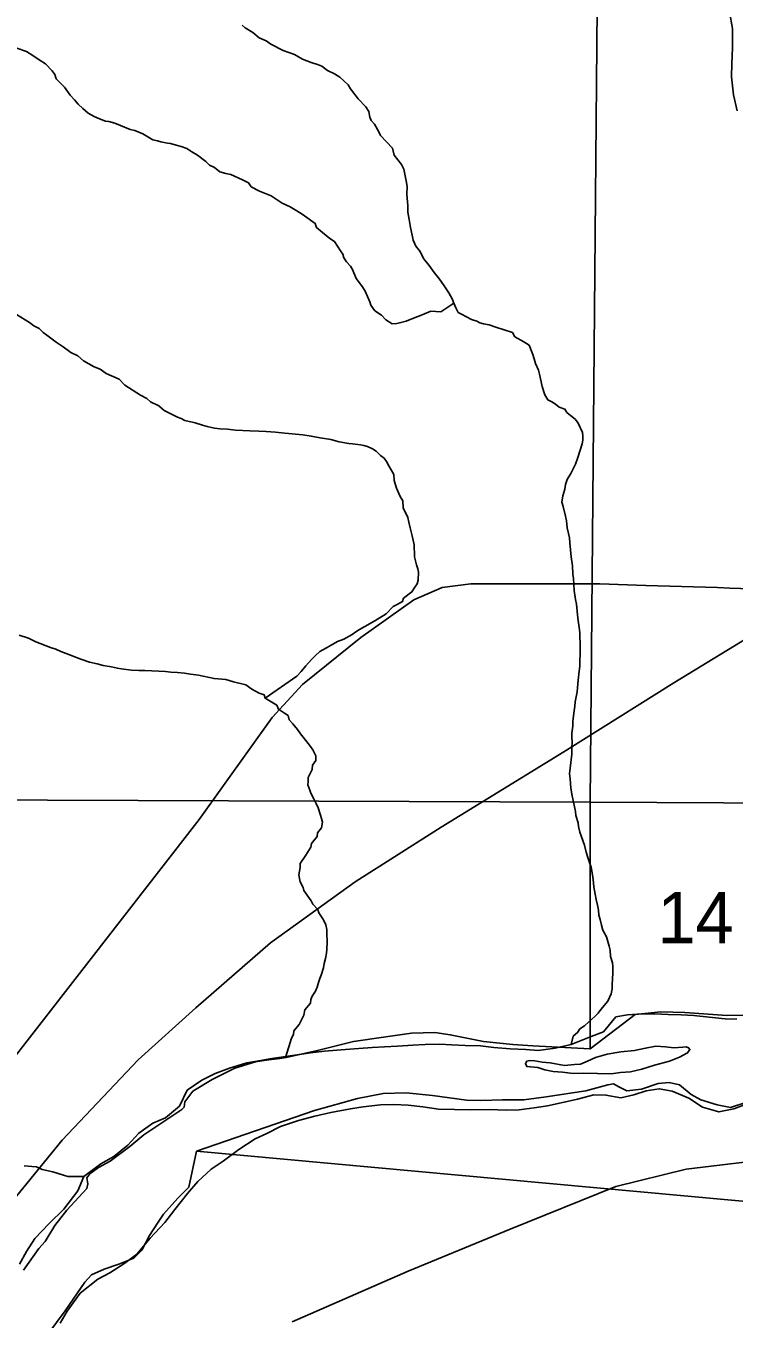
# Model space of a CAD drawing. Extents: x 0 to 34, y 0 to 22.
# Drawn here: x 5.747 to 6.323, y 18.713 to 19.765 of the extents above; entities that cross this region are included whole.
import ezdxf

# ---------------------------------------------------------------- set-up
doc = ezdxf.new("R2010")
doc.units = 0
for name, color, linetype in [('GM_X_Corporation', 7, 'Continuous'), ('GM_X_County_Road', 7, 'Continuous'), ('GM_X_Major_River', 7, 'Continuous'), ('GM_X_Minor_River', 7, 'Continuous'), ('GM_X_Rail_Line', 7, 'Continuous'), ('GM_X_Section_Text', 7, 'Continuous')]:
    doc.layers.add(name, color=color, linetype=linetype)

msp = doc.modelspace()

# ---------------------------------------------------------------- linework, layer by layer
at = {"layer": 'GM_X_Corporation'}
for points in [[(5.1838, 20.1584), (6.2147, 20.1499), (6.2057, 19.1338), (5.1759, 19.1377)], [(6.2147, 20.1499), (7.2322, 20.1409), (7.2228, 19.1563), (7.1813, 19.1288), (6.2057, 19.1338)]]:
    msp.add_lwpolyline(points, close=True, dxfattribs=at)
for points in [[(5.1759, 19.1377), (6.2057, 19.1338), (6.2057, 18.9402), (6.2056, 18.9331), (6.1591, 18.9356), (6.1428, 18.9367), (6.119, 18.9391), (6.0918, 18.9446), (6.0794, 18.9464), (6.0604, 18.946), (6.0376, 18.9427), (6.0133, 18.9391), (5.984, 18.9317), (5.9585, 18.9262), (5.9532, 18.9252), (5.9421, 18.9239), (5.9334, 18.9226), (5.9166, 18.9173), (5.8983, 18.9082), (5.8825, 18.8987), (5.8759, 18.8901), (5.8754, 18.8856), (5.8735, 18.8837), (5.8427, 18.8632), (5.8312, 18.8536), (5.8154, 18.8418), (5.8058, 18.8367), (5.7989, 18.8316), (5.7962, 18.8282), (5.7972, 18.8233), (5.7963, 18.8195), (5.7801, 18.802), (5.7703, 18.7894), (5.7625, 18.7763), (5.7574, 18.7707), (5.7449, 18.7532)], [(6.3327, 18.9606), (6.3168, 18.9602), (6.2827, 18.9628), (6.2631, 18.9633), (6.2422, 18.9611), (6.2056, 18.9331), (6.2057, 18.9402), (6.2057, 19.1338), (7.1813, 19.1288)], [(6.7468, 18.7711), (5.8856, 18.8498), (5.9814, 18.8829), (6.0165, 18.8928), (6.0374, 18.8969), (6.056, 18.8973), (6.0775, 18.8953), (6.1051, 18.8913), (6.1168, 18.891), (6.1343, 18.8918), (6.1517, 18.8918), (6.1699, 18.894), (6.2022, 18.899), (6.2201, 18.904), (6.2247, 18.9046), (6.2295, 18.9019), (6.2355, 18.8991), (6.2473, 18.9003), (6.261, 18.905), (6.2698, 18.9059), (6.2784, 18.9038), (6.2877, 18.8961), (6.2956, 18.8917), (6.3088, 18.8877), (6.3197, 18.8855), (6.3323, 18.8894)], [(5.7386, 18.6518), (5.7481, 18.6739), (5.7533, 18.6863), (5.7584, 18.6927), (5.7787, 18.7199), (5.7947, 18.7434), (5.8001, 18.7493), (5.8105, 18.754), (5.8223, 18.758), (5.8345, 18.763), (5.8411, 18.7693), (5.8474, 18.7813), (5.8537, 18.7914), (5.8588, 18.7988), (5.8704, 18.8118), (5.8793, 18.8207), (5.8856, 18.8498), (6.7468, 18.7711), (6.6697, 17.7728), (6.0867, 17.8254), (5.7275, 17.9786)]]:
    msp.add_lwpolyline(points, dxfattribs=at)
at = {"layer": 'GM_X_County_Road'}
for points in [[(5.6928, 18.8692), (5.8878, 19.1197), (5.947, 19.2028), (5.9718, 19.2296), (6.0192, 19.2677), (6.0622, 19.2985), (6.0854, 19.3084), (6.1086, 19.3114), (6.2134, 19.3114), (6.2509, 19.3102), (6.3093, 19.3084), (6.3193, 19.308), (6.4232, 19.3046)], [(5.9634, 18.7111), (6.0575, 18.7524), (6.1407, 18.7864), (6.2264, 18.8212), (6.2838, 18.8353), (6.3516, 18.8433), (6.5744, 18.8637), (6.6801, 18.8728), (6.8006, 18.8851), (6.882, 18.9065), (6.9447, 18.9302), (7.0662, 18.982), (7.0748, 18.9856), (7.0823, 18.9886), (7.0895, 18.9911), (7.0951, 18.993), (7.1022, 18.9949), (7.1156, 18.998), (7.1303, 19.0001), (7.1684, 18.9978), (7.1744, 18.9974)]]:
    msp.add_lwpolyline(points, dxfattribs=at)
at = {"layer": 'GM_X_Major_River'}
for points in [[(6.3248, 18.9573), (6.3153, 18.9575), (6.3024, 18.9589), (6.2899, 18.9602), (6.2797, 18.9608), (6.2691, 18.961), (6.2581, 18.9616), (6.2478, 18.9615), (6.2361, 18.9609), (6.2266, 18.9592), (6.2164, 18.9469), (6.2065, 18.9433), (6.1901, 18.9367), (6.1771, 18.9336), (6.1634, 18.9319), (6.1532, 18.9325), (6.1407, 18.9331), (6.1274, 18.9342), (6.1165, 18.9355), (6.104, 18.9358), (6.093, 18.9364), (6.0835, 18.9369), (6.0714, 18.9368), (6.0615, 18.9362), (6.049, 18.9353), (6.0383, 18.9348), (6.0284, 18.9342), (6.0102, 18.933), (5.9996, 18.9321), (5.9897, 18.9312), (5.9783, 18.9299), (5.9581, 18.9269), (5.9467, 18.9252), (5.9361, 18.9235), (5.9265, 18.9218), (5.9124, 18.9175), (5.9006, 18.9132), (5.8899, 18.9077), (5.8779, 18.8995), (5.8716, 18.8864), (5.8604, 18.8771), (5.8501, 18.8727), (5.8385, 18.8646), (5.8296, 18.8549), (5.8184, 18.8456), (5.8077, 18.8397), (5.7938, 18.8293), (5.789, 18.8176), (5.7777, 18.8027), (5.7657, 18.7911), (5.7541, 18.7788), (5.7474, 18.7683), (5.7416, 18.7581)], [(6.1601, 18.9183), (6.1631, 18.9179), (6.1688, 18.9162), (6.1756, 18.9146), (6.1832, 18.9141), (6.1919, 18.9131), (6.2002, 18.9133), (6.2116, 18.9131), (6.2226, 18.9129), (6.2302, 18.9139), (6.2385, 18.9145), (6.2477, 18.9166), (6.258, 18.9198), (6.2702, 18.923), (6.2782, 18.9263), (6.2848, 18.9299), (6.2867, 18.9326), (6.2856, 18.9341), (6.2837, 18.9349), (6.2811, 18.9346), (6.2738, 18.934), (6.267, 18.9348), (6.2591, 18.9354), (6.2507, 18.9336), (6.2416, 18.9319), (6.2305, 18.9306), (6.2195, 18.9289), (6.21, 18.9261), (6.2035, 18.9232), (6.1977, 18.9206), (6.1928, 18.9203), (6.1848, 18.9197), (6.1731, 18.9219), (6.1666, 18.9224), (6.1606, 18.9233), (6.1564, 18.9237)], [(6.1564, 18.9237), (6.1541, 18.923), (6.153, 18.9211), (6.1541, 18.9188), (6.1601, 18.9183)], [(5.7747, 18.71), (5.7802, 18.7197), (5.7908, 18.7344), (5.8054, 18.7458), (5.815, 18.751), (5.8273, 18.7587), (5.8369, 18.7661), (5.8478, 18.7792), (5.8598, 18.7919), (5.868, 18.8024), (5.8781, 18.8155), (5.8867, 18.8252), (5.8975, 18.8353), (5.9071, 18.8419), (5.9198, 18.8512), (5.9333, 18.86), (5.9428, 18.8644), (5.9539, 18.8699), (5.9685, 18.8749), (5.9818, 18.8785), (5.9948, 18.8813), (6.0107, 18.8844), (6.021, 18.8861), (6.0351, 18.8877), (6.0461, 18.8879), (6.0575, 18.8873), (6.0696, 18.8859), (6.0824, 18.8841), (6.1082, 18.8836), (6.1238, 18.8837), (6.1374, 18.8834), (6.148, 18.8836), (6.1602, 18.8852), (6.1709, 18.8869), (6.1846, 18.8897), (6.1952, 18.8922), (6.2086, 18.8957), (6.2184, 18.8955), (6.2305, 18.8934), (6.2412, 18.8958), (6.2511, 18.899), (6.2618, 18.9007), (6.2724, 18.8986), (6.2859, 18.893), (6.2971, 18.8856), (6.3103, 18.8819), (6.3225, 18.8843), (6.334, 18.8887)]]:
    msp.add_lwpolyline(points, dxfattribs=at)
at = {"layer": 'GM_X_Minor_River'}
for points in [[(6.319, 19.7768), (6.3214, 19.7631), (6.3214, 19.7475), (6.3208, 19.7346), (6.3206, 19.7239), (6.3222, 19.7091), (6.3253, 19.6961)], [(6.1775, 19.4575), (6.1745, 19.4594), (6.1711, 19.461), (6.1689, 19.4651), (6.1667, 19.472), (6.1645, 19.4819), (6.1637, 19.4853), (6.1611, 19.4906), (6.16, 19.4944), (6.1589, 19.4979), (6.1559, 19.5055), (6.1518, 19.5082), (6.1443, 19.5124), (6.1424, 19.5159), (6.1288, 19.5202), (6.1235, 19.5221), (6.119, 19.5229), (6.116, 19.5237), (6.1134, 19.5252), (6.1092, 19.5264), (6.1051, 19.5287), (6.1009, 19.5307), (6.0983, 19.5322), (6.0964, 19.536), (6.0949, 19.5398), (6.0934, 19.5432), (6.0908, 19.5482), (6.0886, 19.5513), (6.0863, 19.5547), (6.083, 19.5593), (6.0788, 19.5646), (6.0747, 19.5704), (6.0702, 19.5761), (6.0673, 19.5818), (6.0639, 19.586), (6.0616, 19.591), (6.0609, 19.5951), (6.0595, 19.6012), (6.0584, 19.6077), (6.0573, 19.6138), (6.0573, 19.6191), (6.0566, 19.6282), (6.0567, 19.6346), (6.0559, 19.6392), (6.0541, 19.6487), (6.0523, 19.6525), (6.0463, 19.6602), (6.0448, 19.6659), (6.035, 19.6762), (6.0339, 19.6792), (6.0302, 19.6854), (6.0276, 19.6884), (6.0264, 19.6911), (6.0257, 19.6956), (6.0231, 19.6995), (6.0171, 19.706), (6.0107, 19.714), (6.0089, 19.7174), (6.0021, 19.7236), (5.9976, 19.7263), (5.9919, 19.729), (5.9874, 19.7324), (5.9848, 19.7336), (5.9787, 19.7355), (5.9716, 19.7383), (5.9652, 19.7421), (5.9561, 19.7452), (5.946, 19.7503), (5.9422, 19.753), (5.9365, 19.7557), (5.9313, 19.7599), (5.9252, 19.7637), (5.9226, 19.766)], [(6.0949, 19.5398), (6.0842, 19.5327), (6.076, 19.5332), (6.0691, 19.5302), (6.0619, 19.5276), (6.0559, 19.525), (6.0517, 19.5239), (6.0483, 19.5232), (6.0445, 19.5228), (6.0396, 19.5263), (6.0359, 19.5301), (6.0306, 19.5336), (6.0272, 19.5382), (6.0265, 19.5408), (6.0228, 19.5496), (6.0205, 19.553), (6.0153, 19.5599), (6.0123, 19.5671), (6.0108, 19.5698), (6.0074, 19.5733), (6.0052, 19.5767), (6.0045, 19.5797), (6.0026, 19.5824), (5.9977, 19.59), (5.994, 19.5924), (5.9879, 19.5973), (5.9831, 19.6012), (5.982, 19.6046), (5.9733, 19.6108), (5.9707, 19.6127), (5.9643, 19.6165), (5.9616, 19.6181), (5.9552, 19.6212), (5.9496, 19.625), (5.9462, 19.627), (5.9368, 19.6308), (5.93, 19.6343), (5.9277, 19.6377), (5.9228, 19.6401), (5.9134, 19.6443), (5.9093, 19.6451), (5.9044, 19.6467), (5.9002, 19.6501), (5.8961, 19.6521), (5.8931, 19.6551), (5.8863, 19.6601), (5.8818, 19.6628), (5.8776, 19.6655), (5.8731, 19.6671), (5.869, 19.6683), (5.8644, 19.6695), (5.8618, 19.6699), (5.8565, 19.671), (5.8539, 19.6718), (5.8501, 19.6726), (5.8418, 19.6776), (5.8354, 19.6803), (5.8316, 19.6811), (5.8237, 19.6843), (5.8192, 19.6862), (5.8143, 19.6874), (5.8116, 19.6878), (5.8067, 19.6897), (5.8022, 19.6917), (5.7973, 19.6944), (5.7932, 19.6982), (5.7894, 19.7016), (5.7864, 19.7051), (5.7827, 19.7089), (5.7782, 19.7154), (5.7714, 19.7223), (5.7703, 19.7257), (5.7681, 19.7288), (5.7628, 19.7345), (5.7575, 19.7376), (5.7523, 19.7411), (5.7474, 19.7445), (5.7395, 19.7473)], [(5.9413, 19.2184), (5.9672, 19.2364), (5.9706, 19.2402), (5.9744, 19.2447), (5.979, 19.2499), (5.982, 19.2529), (5.9858, 19.2563), (5.9912, 19.2593), (5.995, 19.2615), (6.0003, 19.2645), (6.0052, 19.2664), (6.012, 19.2701), (6.0151, 19.2724), (6.0181, 19.2742), (6.0223, 19.2768), (6.0306, 19.2813), (6.0398, 19.2869), (6.0455, 19.2929), (6.0481, 19.2944), (6.0531, 19.297), (6.0539, 19.2997), (6.0607, 19.3049), (6.063, 19.3087), (6.0649, 19.3113), (6.0657, 19.3144), (6.0661, 19.3208), (6.0654, 19.3235), (6.0643, 19.3269), (6.0628, 19.3334), (6.0628, 19.3364), (6.0625, 19.3406), (6.0625, 19.3432), (6.061, 19.3505), (6.0592, 19.3569), (6.0581, 19.3615), (6.0574, 19.3653), (6.0536, 19.3733), (6.0533, 19.379), (6.0511, 19.3824), (6.0481, 19.3893), (6.0462, 19.3954), (6.0459, 19.4003), (6.0418, 19.4075), (6.0399, 19.411), (6.038, 19.4136), (6.035, 19.4159), (6.0317, 19.4194), (6.0286, 19.4213), (6.0245, 19.4232), (6.0215, 19.424), (6.0188, 19.4244), (6.0124, 19.4253), (6.0094, 19.4257), (6.0015, 19.4269), (5.9947, 19.4288), (5.986, 19.4301), (5.9788, 19.4316), (5.972, 19.4325), (5.9573, 19.4341), (5.9497, 19.4349), (5.9421, 19.4354), (5.9361, 19.4355), (5.9289, 19.4359), (5.9172, 19.4364), (5.9108, 19.4372), (5.9047, 19.4376), (5.9002, 19.4381), (5.8941, 19.4393), (5.8904, 19.4404), (5.8843, 19.4424), (5.876, 19.4444), (5.873, 19.4459), (5.87, 19.4471), (5.8591, 19.4525), (5.8549, 19.4563), (5.8482, 19.4594), (5.8452, 19.4621), (5.8399, 19.4648), (5.8271, 19.4729), (5.8226, 19.4779), (5.812, 19.4825), (5.8071, 19.486), (5.8022, 19.4879), (5.7936, 19.4929), (5.7891, 19.4968), (5.7834, 19.4995), (5.777, 19.5041), (5.7714, 19.5079), (5.7638, 19.5137), (5.7608, 19.516), (5.7575, 19.5191), (5.7533, 19.5214), (5.7496, 19.5241), (5.739, 19.5306)], [(6.1901, 18.9367), (6.1919, 18.9434), (6.1954, 18.9464), (6.1973, 18.9494), (6.2011, 18.952), (6.2045, 18.955), (6.2094, 18.9595), (6.2121, 18.9622), (6.2144, 18.9652), (6.2201, 18.9719), (6.2228, 18.978), (6.2236, 18.9821), (6.2236, 18.9856), (6.2241, 18.9947), (6.2241, 19), (6.2238, 19.003), (6.2223, 19.0083), (6.2219, 19.0133), (6.2212, 19.0167), (6.219, 19.0243), (6.216, 19.0296), (6.2149, 19.0338), (6.2138, 19.0384), (6.2127, 19.0418), (6.2123, 19.046), (6.2116, 19.0501), (6.2105, 19.0547), (6.2098, 19.0589), (6.2087, 19.065), (6.208, 19.071), (6.2076, 19.0748), (6.2065, 19.0809), (6.2051, 19.0847), (6.2039, 19.0881), (6.2025, 19.0931), (6.201, 19.0988), (6.1973, 19.1095), (6.1962, 19.114), (6.1958, 19.1171), (6.194, 19.1231), (6.1936, 19.1262), (6.1918, 19.1353), (6.1911, 19.1391), (6.19, 19.1452), (6.1893, 19.1528), (6.1889, 19.1569), (6.1894, 19.1615), (6.1906, 19.1729), (6.1906, 19.1785), (6.191, 19.1823), (6.1907, 19.1869), (6.1907, 19.1899), (6.1915, 19.1956), (6.1915, 19.1994), (6.1923, 19.2062), (6.1931, 19.2119), (6.1935, 19.2153), (6.1951, 19.2236), (6.1955, 19.2301), (6.1959, 19.2331), (6.1967, 19.2403), (6.1972, 19.2445), (6.1972, 19.249), (6.1976, 19.254), (6.1976, 19.2597), (6.1973, 19.2718), (6.1966, 19.276), (6.1955, 19.2836), (6.1945, 19.295), (6.1938, 19.2988), (6.1927, 19.306), (6.192, 19.3158), (6.1916, 19.3193), (6.1913, 19.3261), (6.1902, 19.3333), (6.1892, 19.3447), (6.1888, 19.3489), (6.187, 19.3569), (6.1863, 19.3626), (6.1856, 19.3664), (6.1837, 19.3743), (6.1826, 19.3778), (6.1834, 19.3831), (6.185, 19.3884), (6.1857, 19.3922), (6.1869, 19.3963), (6.19, 19.4012), (6.1938, 19.4088), (6.1957, 19.4141), (6.1992, 19.4254), (6.1996, 19.4284), (6.1996, 19.4315), (6.1993, 19.4345), (6.1959, 19.4421), (6.1937, 19.4452), (6.1866, 19.4509), (6.1851, 19.4536), (6.1805, 19.4552), (6.1775, 19.4575)], [(5.7752, 19.2564), (5.7711, 19.2583), (5.7669, 19.2595), (5.7548, 19.2642), (5.7488, 19.2673), (5.7413, 19.2696)], [(5.9581, 18.9269), (5.9627, 18.9417), (5.9643, 18.9447), (5.9647, 18.9478), (5.9689, 18.953), (5.9727, 18.9606), (5.9735, 18.9648), (5.9781, 18.9704), (5.9785, 18.9734), (5.9796, 18.9761), (5.9823, 18.9802), (5.9835, 18.9832), (5.9846, 18.987), (5.9858, 18.9904), (5.9869, 18.9931), (5.9889, 18.9991), (5.9893, 19.0025), (5.9904, 19.0067), (5.9912, 19.0109), (5.9916, 19.0139), (5.9917, 19.0203), (5.9914, 19.0272), (5.9914, 19.0302), (5.9907, 19.034), (5.9888, 19.0382), (5.985, 19.0439), (5.9843, 19.0466), (5.9802, 19.0508), (5.9787, 19.0535), (5.9727, 19.0619), (5.9723, 19.0645), (5.9697, 19.0691), (5.9694, 19.0717), (5.9686, 19.0748), (5.9698, 19.0808), (5.9698, 19.0839), (5.9744, 19.0907), (5.9786, 19.0971), (5.979, 19.1001), (5.9836, 19.1058), (5.984, 19.1088), (5.9871, 19.1129), (5.9879, 19.1175), (5.9871, 19.1205), (5.9864, 19.1232), (5.9845, 19.1293), (5.9827, 19.1327), (5.9812, 19.1361), (5.9786, 19.1411), (5.9778, 19.1437), (5.976, 19.1479), (5.9764, 19.1506), (5.9764, 19.154), (5.9795, 19.1604), (5.9799, 19.1638), (5.9825, 19.1676), (5.9826, 19.1714), (5.98, 19.1763), (5.9781, 19.179), (5.9743, 19.184), (5.9702, 19.1893), (5.9676, 19.1928), (5.9639, 19.1974), (5.9609, 19.2008), (5.9601, 19.2042), (5.9571, 19.2061), (5.9522, 19.2096), (5.9507, 19.2126), (5.9413, 19.2184), (5.9406, 19.2211), (5.9364, 19.2226), (5.9304, 19.2257), (5.9255, 19.2292), (5.9157, 19.2316), (5.9093, 19.2335), (5.8998, 19.2344), (5.887, 19.2371), (5.8806, 19.238), (5.8757, 19.2388), (5.87, 19.2392), (5.8647, 19.2396), (5.8602, 19.24), (5.8549, 19.2405), (5.8435, 19.241), (5.8386, 19.241), (5.8326, 19.2411), (5.8243, 19.2423), (5.8212, 19.2427), (5.8163, 19.2439), (5.8095, 19.2451), (5.8046, 19.2463), (5.7986, 19.2478), (5.7914, 19.2502), (5.7794, 19.2548), (5.7752, 19.2564)], [(5.7938, 18.8293), (5.7808, 18.8292), (5.7774, 18.8304), (5.7687, 18.8332), (5.76, 18.8351), (5.7555, 18.8371), (5.7517, 18.8375), (5.7453, 18.8379)]]:
    msp.add_lwpolyline(points, dxfattribs=at)
at = {"layer": 'GM_X_Rail_Line'}
msp.add_lwpolyline([(5.7307, 18.8031), (5.7764, 18.8589), (5.8381, 18.9243), (5.8849, 18.9665), (5.9458, 19.0195), (6.0144, 19.069), (6.0845, 19.1134), (6.1841, 19.1748), (6.2736, 19.231), (6.831, 19.571), (6.9536, 19.6458), (7.2249, 19.8148)], dxfattribs=at)

# ---------------------------------------------------------------- texts
at = {"layer": 'GM_X_Section_Text'}
msp.add_text('14', height=0.04186, rotation=0, dxfattribs=at).set_placement((6.2602, 19.019))

doc.saveas('drawing.dxf')
